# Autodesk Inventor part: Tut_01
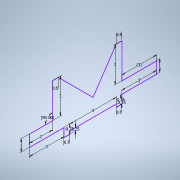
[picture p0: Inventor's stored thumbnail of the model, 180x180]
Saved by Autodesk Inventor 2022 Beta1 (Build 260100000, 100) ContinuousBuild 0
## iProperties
Created: 2019-02
Part Number: Tut_01
Material: Generic
Document SubType Name: Modeling
Designer: LENOVO-CADCIM
Density: 1 g/cm^3
Appearance: Default
Author: LENOVO-CADCIM
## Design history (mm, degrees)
sketch "Sketch1"
  geometry: L1 (0, 0)-(3, 3); L2 (3, 3)-(3, 3.5); L3 (3, 3.5)-(0, 3.5); L4 (0, 3.5)-(0, 5.5); L5 (0, 5.5)-(-1, 5.5); L6 (-1, 5.5)-(-1, 2.5); L7 (-1, 2.5)-(-1.75, 2.5); L8 (-1.75, 2.5)-(-1.75, 2); L9 (-1.75, 2)-(-1.5, 2); L10 (-1.5, 2)-(-1.5, -2); L11 (-1.5, -2)-(-1.75, -2); L12 (-1.75, -2)-(-1.75, -2.5); L13 (-1.75, -2.5)-(-1.01, -2.5); L14 (-1.01, -2.5)-(-1.01, -5.5); L15 (-1.01, -5.5)-(-0.01, -5.5); L16 (-0.01, -5.5)-(-0.01, -2.5); L17 (-0.01, -2.5)-(2.99, -2.5); L18 (2.99, -2.5)-(2.99, -2); L19 (2.99, -2)-(0, 0)
  constraints: 38 end point, 10 perpendicular, 3 point on line, 2 horizontal, 2 vertical
  dimensions: "d0" = 0.5 distance of L1.end L2.end; "d1" = 3 distance of L2.end L3.end; "d2" = 2 distance of L3.end L4.end; "d3" = 90 deg angle of L3 L4 (derived); "d4" = 1 distance of L4.end L5.end; "d5" = 3 distance of L5.end L6.end; "d6" = 0.75 distance of L6.end L7.end; "d7" = 0.5 distance of L7.end L8.end; "d8" = 0.25 distance of L8.end L9.end; "d9" = 4 distance of L9.end L10.end; "d10" = 0.25 distance of L10.end L11.end; "d11" = 0.5 distance of L11.end L12.end; "d12" = 0.74 distance of L12.end L13.end; "d13" = 3 distance of L13.end L14.end; "d14" = 1 distance of L14.end L15.end; "d15" = 3 distance of L15.end L16.end (derived); "d16" = 3 distance of L16.end L17.end; "d17" = 0.5 distance of L17.end L18.end
